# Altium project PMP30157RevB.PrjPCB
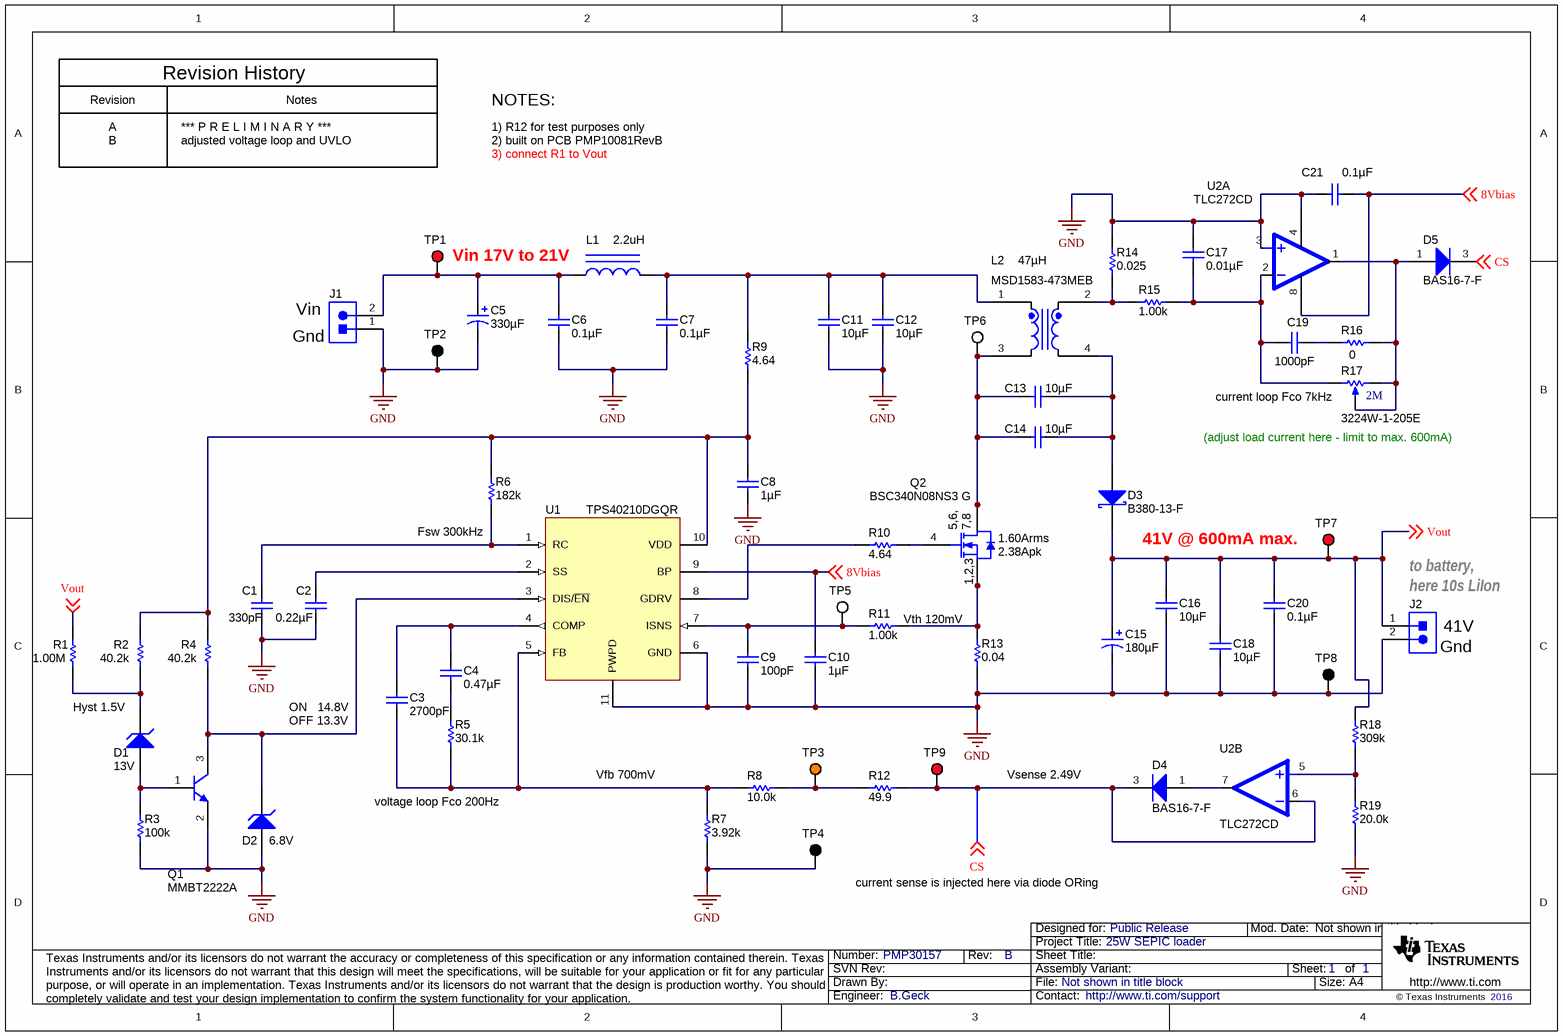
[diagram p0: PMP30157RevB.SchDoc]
TechSupport: http://www.ti.com/support; SCH_Rev: B; PRJ_Title: 25W SEPIC loader; PRJ_Number: PMP30157; PRJ_Engineer: B.Geck; PRJ_Customer: Public Release; PCB_Rev: A; PCB_Layout: B.Geck; CopyrightYear: 2016
1 sheet, 62 parts. Net scope: global (net labels, ports and power ports of the same name join across sheets).

## Sheet PMP30157RevB.SchDoc
size A4; Date: Not shown in title block; ApprovedBy: Not shown in title block; CheckedBy: Not shown in title block; Author: Not shown in title block; CompanyName: Not shown in title block; Engineer: Not shown in title block; Organization: Not shown in title block; Address1: Not shown in title block; Address2: Not shown in title block; Address3: Not shown in title block; Address4: Not shown in title block; DocumentNumber: 1; Revision: Use project parameter SCH_Rev; SheetNumber: 1; SheetTotal: 1; PageSetup: Record=PageOptions¦CenterHorizontal=True¦CenterVertical=True¦PrintScale=0.70¦XCorrection=1.00¦YCorrection=1.00¦PrintKind=0¦BorderSize=5000000¦LeftOffset=0¦BottomOffset=0¦Orientation=2¦PaperLength=1000¦PaperWidth=1000¦Scale=100¦PaperSource=15¦PrintQuality=600¦MediaType=1¦DitherType=10¦PrintScaleMode=1¦PaperKind=A4

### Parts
C1  ValueDisplayed: 330pF  [0603]  (hidden comment: GRM188R71H331KA01D)
C2  ValueDisplayed: 0.22µF  [0603]  (hidden comment: GRM188R71E224KA88D)
C3  ValueDisplayed: 2700pF  [0603]  (hidden comment: GRM188R71E272KA01D)
C4  ValueDisplayed: 0.47µF  [0603]  (hidden comment: GRM188R71C474KA88D)
C5  ValueDisplayed: 330µF  [SM_RADIAL_G]  (hidden comment: EEE-FK1V331P)
C6  ValueDisplayed: 0.1µF  [0603]  (hidden comment: GRM188R71H104KA93D)
C7  ValueDisplayed: 0.1µF  [0603]  (hidden comment: GRM188R71H104KA93D)
C8  ValueDisplayed: 1µF  [0805_HV]  (hidden comment: GRM21BR71H105KA12L)
C9  ValueDisplayed: 100pF  [0603]  (hidden comment: 06033C101KAT2A)
C10  ValueDisplayed: 1µF  [0603]  (hidden comment: GRM188R71E105KA12D)
C11  ValueDisplayed: 10µF  [1210]  (hidden comment: GRM32ER71H106KA12L)
C12  ValueDisplayed: 10µF  [1210]  (hidden comment: GRM32ER71H106KA12L)
C13  ValueDisplayed: 10µF  [1210]  (hidden comment: GRM32ER71H106KA12L)
C14  ValueDisplayed: 10µF  [1210]  (hidden comment: GRM32ER71H106KA12L)
C15  ValueDisplayed: 180µF  [CR_1000x1270]  (hidden comment: PCR1H181MCL1GS)
C16  ValueDisplayed: 10µF  [1210]  (hidden comment: GRM32ER71H106KA12L)
C17  ValueDisplayed: 0.01µF  [0603]  (hidden comment: GRM188R71H103KA01D)
C18  ValueDisplayed: 10µF  [1210]  (hidden comment: GRM32ER71H106KA12L)
C19  ValueDisplayed: 1000pF  [0603]  (hidden comment: GRM188R71H102KA01D)
C20  ValueDisplayed: 0.1µF  [0603]  (hidden comment: GRM188R71H104KA93D)
C21  ValueDisplayed: 0.1µF  [0603]  (hidden comment: GCM188R71H104KA57D)
D1  value 13V  [SOD-323]  (hidden comment: CMDZ5243B-NSG)
D2  value 6.8V  [sod-323]  (hidden comment: MMSZ5235BS-7-F)
D3  B380-13-F  [SMC]
D4  BAS16-7-F  [SOT-23]
D5  BAS16-7-F  [SOT-23]
J1  ED555/2DS  [TERM_BLK_ED555-2DS]  (value not drawn)
J2  ED555/2DS  [TERM_BLK_ED555-2DS]  (value not drawn)
L1  value 2.2uH  [WE-SPC_4838]  (hidden comment: 74408943022)
L2  MSD1583-473MEB  ValueDisplayed: 47µH  [IND_MSD1583]
Q1  MMBT2222A  [SOT-23]
Q2  BSC340N08NS3 G  [PG-TDSON-8]
R1  ValueDisplayed: 1.00M  [0603]  (hidden comment: CRCW06031M00FKEA)
R2  ValueDisplayed: 40.2k  [0603]  (hidden comment: CRCW060340K2FKEA)
R3  value 100k  [0603]  (hidden comment: CRCW0603100KFKEA)
R4  ValueDisplayed: 40.2k  [0603]  (hidden comment: CRCW060340K2FKEA)
R5  ValueDisplayed: 30.1k  [0603]  (hidden comment: CRCW060330K1FKEA)
R6  value 182k  [0603]  (hidden comment: CRCW0603182KFKEA)
R7  value 3.92k  [0603]  (hidden comment: CRCW06033K92FKEA)
R8  value 10.0k  [0603]  (hidden comment: CRCW060310K0FKEA)
R9  value 4.64  [0603]  (hidden comment: CRCW06034R64FKEA)
R10  value 4.64  [0603]  (hidden comment: CRCW06034R64FKEA)
R11  value 1.00k  [0603]  (hidden comment: CRCW06031K00FKEA)
R12  value 49.9  [0603]  (hidden comment: CRCW060349R9FKEA)
R13  ValueDisplayed: 0.04  [2010]  (hidden comment: CSRN2010FK40L0)
R14  value 0.025  [2010M]  (hidden comment: CSRN2010FK25L0)
R15  ValueDisplayed: 1.00k  [0603]  (hidden comment: CRCW06031K00FKEA)
R16  ValueDisplayed: 0  [0603]  (hidden comment: CRCW06030000Z0EA)
R17  3224W-1-205E  value 2M  [TRIM_3224W]
R18  ValueDisplayed: 309k  [0603]  (hidden comment: CRCW0603309KFKEA)
R19  value 20.0k  [0603]  (hidden comment: CRCW060320K0FKEA)
TP1  5000  [Keystone5000]  (value not drawn)
TP2  5001  [Keystone5001]  (value not drawn)
TP3  5003  [Keystone5003]  (value not drawn)
TP4  5001  [Keystone5001]  (value not drawn)
TP5  5002  [Keystone5002]  (value not drawn)
TP6  5002  [Keystone5002]  (value not drawn)
TP7  5000  [Keystone5000]  (value not drawn)
TP8  5001  [Keystone5001]  (value not drawn)
TP9  5000  [Keystone5000]  (value not drawn)
U1  TPS40210DGQR  [DGQ0010D_N]
U2  TLC272CD  [D0008A_N]  (parts A,B of 2)

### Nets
GND: C1.2 C2.2 C5.2(-) C6.2 C7.2 C8.2 C9.2 C10.2 C11.2 C12.2 C15.2(-) C16.2 C17.1 C18.2 C20.2 C21.1 D2.2(A) J1.1 J2.2 Q1.2(E) R3.1 R7.1 R13.1 R14.2 R19.1 TP2.1 TP4.1 TP8.1 U1.6(GND) U1.11(PWPD) U2.3(IN+) U2.4(GND)
8Vbias: C10.1 C21.2 U1.9(BP) U2.8(VCC) ; off-sheet 8Vbias
CS: D4.3(K) D5.3(K) R12.2 TP9.1 U2.6(IN-) ; off-sheet CS
Vout: C15.1(+) C16.1 C18.1 C20.1 D3.1(K) J2.1 R1.2 R18.2 TP7.1 ; off-sheet Vout
NetC1_1: C1.1 R6.1 U1.1(RC)
NetC2_1: C2.1 U1.2(SS)
NetC3_1: C3.1 C4.1 U1.4(COMP)
NetC3_2: C3.2 R5.1 R7.2 R8.1 U1.5(FB)
NetC4_2: C4.2 R5.2
NetC5_1: C5.1(+) C6.1 J1.2 L1.1 TP1.1
NetC7_1: C7.1 C11.1 C12.1 L1.2 L2.1 R9.2
NetC8_1: C8.1 R2.2 R4.2 R6.2 R9.1 U1.10(VDD)
NetC9_1: C9.1 R11.1 TP5.1 U1.7(ISNS)
NetC13_1: C13.1 C14.1 L2.3 Q2.5(D) Q2.6(D) Q2.7(D) Q2.8(D) Q2.9(D) TP6.1
NetC13_2: C13.2 C14.2 D3.2(A) L2.4
NetC17_2: C17.2 C19.1 R15.2 R17.1(CCW) U2.2(IN-)
NetC19_2: C19.2 R16.1
NetD1_1: D1.1(K) R1.1 R2.1
NetD1_2: D1.2(A) Q1.1(B) R3.2
NetD2_1: D2.1(K) Q1.3(C) R4.1 U1.3(DIS/~{EN})
NetD4_1: D4.1(A) U2.7(OUT)
NetD5_1: D5.1(A) R16.2 R17.2(WIPER) R17.3(CW) U2.1(OUT1)
NetL2_2: L2.2 R14.1 R15.1
NetQ2_1: Q2.1(S) Q2.2(S) Q2.3(S) R11.2 R13.2
NetQ2_4: Q2.4(G) R10.1
NetR8_2: R8.2 R12.1 TP3.1
NetR10_2: R10.2 U1.8(GDRV)
NetR18_1: R18.1 R19.2 U2.5(IN+)

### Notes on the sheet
- Revision
- Revision History
- Notes
- NOTES:
- A
- B
- *** P R E L I M I N A R Y ***
- adjusted voltage loop and UVLO
- 1) R12 for test purposes only
- 2) built on PCB PMP10081RevB
- 3) connect R1 to Vout
- Vin 17V to 21V
- (near J1) Vin
- (near J1) Gnd
- (near R17) current loop Fco 7kHz
- (near R17) (adjust load current here - limit to max. 600mA)
- (near R6) Fsw 300kHz
- (near Q2) 1.60Arms
- (near Q2) 2.38Apk
- 41V @ 600mA max.
- (near J2) to battery,
- (near J2) here 10s LiIon
- (near R11) Vth 120mV
- (near J2) 41V
- (near J2) Gnd
- Hyst 1.5V
- (near C3) ON   14.8V
- (near C3) OFF 13.3V
- Vfb 700mV
- Vsense 2.49V
- (near R5) voltage loop Fco 200Hz
- (near TP4) current sense is injected here via diode ORing

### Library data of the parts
C1 = GRM188R71H331KA01D: CAP, CERM, 330pF, 50V, +/-10%, X7R, 0603; Manufacturer: MuRata; Polarized: N; CompType: Capacitor; U/M: EA; Cap_F: 0.00000000033; Tolerance_%: 10; Value1: Unknown; VDC_V: 50; TaMin_C: -55; TaMax_C: 125
C2 = GRM188R71E224KA88D: CAP, CERM, 0.22uF, 25V, +/-10%, X7R, 0603; Manufacturer: MuRata; Polarized: N; CompType: Capacitor; U/M: EA; Cap_F: 0.00000022; Tolerance_%: 10; Value1: Unknown; VDC_V: 25; TaMin_C: -55; TaMax_C: 125
C3 = GRM188R71E272KA01D: CAP, CERM, 2700 pF, 25 V, +/- 10%, X7R, 0603; Manufacturer: MuRata; Polarized: N; CompType: Capacitor; Value: 2700pF; U/M: EA; Cap_F: 0.0000000027; Tolerance_%: 10; Value1: Unknown; VDC_V: 25; Value2: 25V; TaMin_C: -55; TaMax_C: 125; SizeArea_mm2: 1.28; SizeAreaWB_mm2: 4.68; SizeX_mm: 1.6; SizeY_mm: 0.8; SizeZ_mm: 1; AEC Category: Q200
C4 = GRM188R71C474KA88D: CAP, CERM, 0.47 µF, 16 V, +/- 10%, X7R, 0603; Manufacturer: MuRata; Polarized: N; CompType: Capacitor; Value: 0.47uF; U/M: EA; Cap_F: 0.00000047; Tolerance_%: 10; Value1: Unknown; VDC_V: 16; Value2: 16V; TaMin_C: -55; TaMax_C: 125; SizeArea_mm2: 1.28; SizeAreaWB_mm2: 4.68; SizeX_mm: 1.6; SizeY_mm: 0.8; SizeZ_mm: 1; AEC Category: Q200
C5 = EEE-FK1V331P: CAP, AL, 330 µF, 35 V, +/- 20%, 0.08 ohm, SMD; Manufacturer: Panasonic; Polarized: Y; CompType: Capacitor; Value: 330uF; U/M: EA; Cap_F: 0.00033; Tolerance_%: 20; VDC_V: 35; Value2: 35V; ESR_ohm: 0.08; IRMS_A: 0.85; TaMin_C: -55; TaMax_C: 105; Cap_Case: G; AEC Category: Q200
C6 C7 C20 = GRM188R71H104KA93D: CAP, CERM, 0.1 µF, 50 V, +/- 10%, X7R, 0603; Manufacturer: MuRata; Polarized: N; CompType: Capacitor; Value: 0.1uF; U/M: EA; Cap_F: 0.0000001; Tolerance_%: 10; Value1: Unknown; VDC_V: 50; Value2: 50V; TaMin_C: -55; TaMax_C: 125
C8 = GRM21BR71H105KA12L: CAP, CERM, 1uF, 50V, +/-10%, X7R, 0805; Manufacturer: MuRata; Polarized: N; CompType: Capacitor; U/M: EA; Cap_F: 0.000001; Tolerance_%: 10; Value1: Unknown; VDC_V: 50; TaMin_C: -55; TaMax_C: 125; Cap_Case: 0805
C9 = 06033C101KAT2A: CAP, CERM, 100pF, 25V, +/-10%, X7R, 0603; Manufacturer: AVX; Polarized: N; CompType: Capacitor; U/M: EA; Cap_F: 0.0000000001; Tolerance_%: 10; Value1: Unknown; VDC_V: 25; TaMin_C: -55; TaMax_C: 125
C10 = GRM188R71E105KA12D: CAP, CERM, 1uF, 25V, +/-10%, X7R, 0603; Manufacturer: MuRata; Polarized: N; CompType: Capacitor; U/M: EA; Cap_F: 0.000001; Tolerance_%: 10; Value1: Unknown; VDC_V: 25; TaMin_C: -55; TaMax_C: 125
C11-C14 C16 C18 = GRM32ER71H106KA12L: CAP, CERM, 10uF, 50V, +/-10%, X7R, 1210; Manufacturer: MuRata; Polarized: N; CompType: Capacitor; U/M: EA; Cap_F: 0.00001; Tolerance_%: 10; Value1: Unknown; VDC_V: 50; TaMin_C: -55; TaMax_C: 125
C15 = PCR1H181MCL1GS: CAP, Aluminum Polymer, 180 µF, 50 V, +/- 20%, 0.019 ohm, SMD, 2-Leads, Dia 10.5mm, Pin Spacing 8mm SMD; Manufacturer: Nichicon; Polarized: Y; CompType: Capacitor; Value: 180uF; U/M: EA; Cap_F: 0.00018; Tolerance_%: 20; VDC_V: 50; Value2: 50V; ESR_ohm: 0.019; IRMS_A: 3.5; TaMin_C: -55; TaMax_C: 125; Cap_Case: 10x12.7mm; AEC Category: Q200; AEC Qualified: N
C17 = GRM188R71H103KA01D: CAP, CERM, 0.01uF, 50V, +/-10%, X7R, 0603; Manufacturer: MuRata; Polarized: N; CompType: Capacitor; U/M: EA; Cap_F: 0.00000001; Tolerance_%: 10; Value1: Unknown; VDC_V: 50; TaMin_C: -55; TaMax_C: 125
C19 = GRM188R71H102KA01D: CAP, CERM, 1000pF, 50V, +/-10%, X7R, 0603; Manufacturer: MuRata; Polarized: N; CompType: Capacitor; U/M: EA; Cap_F: 0.000000001; Tolerance_%: 10; Value1: Unknown; VDC_V: 50; TaMin_C: -55; TaMax_C: 125
C21 = GCM188R71H104KA57D: CAP, CERM, 0.1uF, 50V, +/-10%, X7R, 0603; Manufacturer: MuRata; Polarized: N; CompType: Capacitor; U/M: EA; Cap_F: 0.0000001; Tolerance_%: 10; ESR_Ohm: 0.02; Value1: 0.02 ohm; VDC_V: 50; IRMS_A: 1.84; TaMin_C: -55; TaMax_C: 125
D1 = CMDZ4L7 TR: Diode, Zener, 13 V, 250 mW, SOD-323; Manufacturer: Central Semiconductor; SymbolCreator: a0412235; U/M: EA; Power_W: 0.25; Vz_V: 13; Value1: 0.25W; RJA_CperW: 500; SizeAreaWB_mm2: 8.695; SizeArea_mm2: 3.645; SizeX_mm: 2.7; SizeY_mm: 1.35; SizeZ_mm: 1; AEC Category: Q101
D2 = MMSZ5235BS-7-F: Diode, Zener, 6.8V, 200mW, SOD-323; Manufacturer: Diodes Inc.; SymbolCreator: a0412235; U/M: EA; Power_W: 0.2; Vz_V: 6.8; Value1: 0.2W; RJA_CperW: 350
D3 = B380-13-F: Diode, Schottky, 80 V, 3 A, SMC; Manufacturer: Diodes Inc.; U/M: EA; Vf_V: 0.79; Value: 80V; Value1: 3A; Value2: 0.79V; Io_A: 3; Vr_V: 80; TJmax_C: 125; RJC_CperW: 10; SizeAreaWB_mm2: 83.2686; SizeArea_mm2: 50.5686; SizeX_mm: 8.13; SizeY_mm: 6.22; SizeZ_mm: 2.6; AEC Category: Q101
D4 D5 = BAS16-7-F: Diode, Ultrafast, 75V, 0.3A, SOT-23; Manufacturer: Diodes Inc.; U/M: EA; Vf_V: 1.125; Value2: 1.125V; Io_A: 0.3; Vr_V: 75
J1 J2 = ED555/2DS: Terminal Block, 6A, 3.5mm Pitch, 2-Pos, TH; Manufacturer: On-Shore Technology; SymbolCreator: a0412235; CompType: Connector; U/M: EA
L1 = 74408943022: Inductor, Shielded Drum Core, Ferrite, 2.2 µH, 3 A, 0.026 ohm, SMD; Manufacturer: Wurth Elektronik; Ind_H: 2.2E-6; ValueDisplayed: 2.2µH; Imax_A: 3; Irms: 3A @ 40C rise; Isat: 4.6A @ 35% inductance drop; DCR_ohm: 0.026; Value2: 3A
L2 = MSD1583-473MEB: Coupled inductor, 47 µH, 5.4 A, 0.1 ohm, SMD; Manufacturer: Coilcraft; SymbolCreator: a0412235; Value: 47uH; Ind_H: 47.0E-6; DCR_ohm: 0.1
Q1 = MMBT2222A, Fairchild Semiconductor: Transistor, NPN, 40V, 0.15A, SOT-23; CompType: BJT; PNP: 0; NPN: 1; Vceo_V: 40; Vcesat1_V: 0.3; Value: 0.3V; IcRated_A: 0.15; HfeMax: 300; TaMin_C: -55; TaMax_C: 150; U/M: EA
Q2 = BSC340N08NS3 G: MOSFET, N-CH, 80 V, 23 A, PG-TDSON-8; Manufacturer: Infineon Technologies; Alternate Manufacturer: None; U/M: EA; ChType: N; Value: 80V; VdsMax_V: 80; Value1: 0.065 ohm; Rdson45_ohm: 0.065; Value2: 6.8 nC; QgTyp_nC: 6.8; Vgs_V: 20; IdsMax_A: 23; SizeAreaWB_mm2: 55.131; SizeArea_mm2: 29.351; SizeX_mm: 5.99; SizeY_mm: 4.9; SizeZ_mm: 1.12; AEC Category: Q101
R1 = CRCW06031M00FKEA: RES, 1.00 M, 1%, 0.1 W, 0603; Manufacturer: Vishay-Dale; CompType: Resistor; Value: 1.00Meg; Res_ohm: 1000000; Value_Code: 1M00; Tolerance_%: 1; Power_W: 0.1; Value2: 0.1W; VDC_V: 75; TempCo: 100 ppm/C; SizeArea_mm2: 1.28; SizeX_mm: 1.6; SizeY_mm: 0.8; EIA_Code: E96; U/M: EA; AEC Category: Q200
R2 R4 = CRCW060340K2FKEA: RES, 40.2 k, 1%, 0.1 W, 0603; Manufacturer: Vishay-Dale; CompType: Resistor; Value: 40.2k; Res_ohm: 40200; Value_Code: 40k2; Tolerance_%: 1; Power_W: 0.1; Value2: 0.1W; VDC_V: 75; TempCo: 100 ppm/C; SizeArea_mm2: 1.28; SizeX_mm: 1.6; SizeY_mm: 0.8; EIA_Code: E96; U/M: EA; AEC Category: Q200
R3 = CRCW0603100KFKEA: RES, 100k ohm, 1%, 0.1W, 0603; Manufacturer: Vishay-Dale; CompType: Resistor; Res_ohm: 100000; Tolerance_%: 1; Power_W: 0.1; VDC_V: 75; TempCo: 100 ppm/C; EIA_Code: E96; U/M: EA
R5 = CRCW060330K1FKEA: RES, 30.1 k, 1%, 0.1 W, 0603; Manufacturer: Vishay-Dale; CompType: Resistor; Value: 30.1k; Res_ohm: 30100; Value_Code: 30k1; Tolerance_%: 1; Power_W: 0.1; Value2: 0.1W; VDC_V: 75; TempCo: 100 ppm/C; SizeArea_mm2: 1.28; SizeX_mm: 1.6; SizeY_mm: 0.8; EIA_Code: E96; U/M: EA; AEC Category: Q200
R6 = CRCW0603182KFKEA: RES, 182k ohm, 1%, 0.1W, 0603; Manufacturer: Vishay-Dale; CompType: Resistor; Res_ohm: 182000; Tolerance_%: 1; Power_W: 0.1; VDC_V: 75; TempCo: 100 ppm/C; EIA_Code: E96; U/M: EA
R7 = CRCW06033K92FKEA: RES, 3.92k ohm, 1%, 0.1W, 0603; Manufacturer: Vishay-Dale; CompType: Resistor; Res_ohm: 3920; Value_Code: 3k92; Tolerance_%: 1; Power_W: 0.1; VDC_V: 75; TempCo: 100 ppm/C; EIA_Code: E96; U/M: EA
R8 = CRCW060310K0FKEA: RES, 10.0k ohm, 1%, 0.1W, 0603; Manufacturer: Vishay-Dale; CompType: Resistor; Res_ohm: 10000; Value_Code: 10k0; Tolerance_%: 1; Power_W: 0.1; VDC_V: 75; TempCo: 100 ppm/C; EIA_Code: E96; U/M: EA
R9 R10 = CRCW06034R64FKEA: RES, 4.64 ohm, 1%, 0.1W, 0603; Manufacturer: Vishay-Dale; CompType: Resistor; Value_Code: 4R64; Tolerance_%: 1; Power_W: 0.1; VDC_V: 75; TempCo: 100 ppm/C; EIA_Code: E96; U/M: EA
R11 = CRCW06031K00FKEA: RES, 1.00k ohm, 1%, 0.1W, 0603; Manufacturer: Vishay-Dale; CompType: Resistor; Res_ohm: 1000; Value_Code: 1k00; Tolerance_%: 1; Power_W: 0.1; VDC_V: 75; TempCo: 100 ppm/C; EIA_Code: E96; U/M: EA
R12 = CRCW060349R9FKEA: RES, 49.9 ohm, 1%, 0.1W, 0603; Manufacturer: Vishay-Dale; CompType: Resistor; Value_Code: 49R9; Tolerance_%: 1; Power_W: 0.1; VDC_V: 75; TempCo: 100 ppm/C; EIA_Code: E96; U/M: EA
R13 = CSRN2010FK40L0: RES, 0.04, 1%, 1 W, 2010; Manufacturer: Stackpole Electronics Inc; CompType: Resistor; Value: 0.04; Value_Code: R040; Tolerance_%: 1; Value2: 1W; TempCo: 250 ppm/C; SizeArea_mm2: 12.5; SizeX_mm: 5; SizeY_mm: 2.5; SizeZ_mm: 1.66; U/M: EA; AEC Category: Q200
R14 = CSRN2010FK25L0: RES, 0.025 ohm, 1%, 1W, 2010; Manufacturer: Stackpole Electronics Inc; CompType: Resistor; Value_Code: R025; Tolerance_%: 1; TempCo: 250 ppm/C; EIA_Code: E96; U/M: EA
R15 = CRCW06031K00FKEA: RES, 1.00 k, 1%, 0.1 W, 0603; Manufacturer: Vishay-Dale; CompType: Resistor; Value: 1.00k; Res_ohm: 1000; Value_Code: 1k00; Tolerance_%: 1; Power_W: 0.1; Value2: 0.1W; VDC_V: 75; TempCo: 100 ppm/C; EIA_Code: E96; U/M: EA
R16 = CRCW06030000Z0EA: RES, 0, 5%, 0.1 W, 0603; Manufacturer: Vishay-Dale; CompType: Resistor; Value: 0; Value_Code: 0000; Tolerance_%: 5; Power_W: 0.1; Value2: 0.1W; VDC_V: 75; TempCo: 200 ppm/C; EIA_Code: E24; U/M: EA
R17 = 3224W-1-205E: TRIMMER 2M OHM 0.25W SMD; Manufacturer: Bourns; Sim Note: Enter the Resistance value and the set point into parameter fields.; SymbolCreator: a0412235
R18 = CRCW0603309KFKEA: RES, 309 k, 1%, 0.1 W, 0603; Manufacturer: Vishay-Dale; CompType: Resistor; Value: 309k; Res_ohm: 309000; Tolerance_%: 1; Power_W: 0.1; Value2: 0.1W; VDC_V: 75; TempCo: 100 ppm/C; SizeArea_mm2: 1.28; SizeX_mm: 1.6; SizeY_mm: 0.8; EIA_Code: E96; U/M: EA; AEC Category: Q200
R19 = CRCW060320K0FKEA: RES, 20.0k ohm, 1%, 0.1W, 0603; Manufacturer: Vishay-Dale; CompType: Resistor; Res_ohm: 20000; Value_Code: 20k0; Tolerance_%: 1; Power_W: 0.1; VDC_V: 75; TempCo: 100 ppm/C; EIA_Code: E96; U/M: EA
TP1 TP7 TP9 = 5000: Test Point, Miniature, Red, TH; Manufacturer: Keystone; CompType: Test Point Loop; U/M: EA
TP2 TP4 TP8 = 5001: Test Point, Miniature, Black, TH; Manufacturer: Keystone; CompType: Test Point Loop; U/M: EA
TP3 = 5003: Test Point, Miniature, Orange, TH; Manufacturer: Keystone; CompType: Test Point Loop; U/M: EA
TP5 TP6 = 5002: Test Point, Miniature, White, TH; Manufacturer: Keystone; CompType: Test Point Loop; U/M: EA
U1 = TPS40210DGQR: 4.5-V TO 52-V INPUT CURRENT MODE BOOST CONTROLLER, DGQ0010D; Alternate Manufacturer: Texas Instruments; SymbolCreator: a0412235; CompType: IC; U/M: EA
U2 = TLC272CD: IC, Precision Dual Operational Amplifiers; Manufacturer: TI; Alternate Manufacturer: None; Area: 75900

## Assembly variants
001: all parts fitted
